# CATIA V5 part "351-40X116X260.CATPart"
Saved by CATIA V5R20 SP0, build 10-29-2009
Part number: 351-40X116X260
Definition: NONE
Nomenclature: 351-40X116X260
Source: Unknown
Description: 351-40X116X260
Bounding box of the stored display mesh (mm): x -8 to 252, y -26 to 26, z -26 to 26
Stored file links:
  C:\Users\Utente\Desktop\IO LAVORO\3D X SITO CF\X SITO\PLASTICA\351\351-40X116X260.CATPart

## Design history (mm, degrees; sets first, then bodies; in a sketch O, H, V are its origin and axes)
Body1 "351-40X116X260" (main body)
  Solid1: solid without history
